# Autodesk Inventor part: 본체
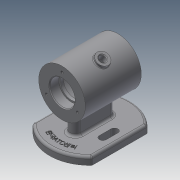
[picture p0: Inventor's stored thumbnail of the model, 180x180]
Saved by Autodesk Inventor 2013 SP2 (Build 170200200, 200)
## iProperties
Created: 2022-02
Part Number: 본체
Material: Generic
Document SubType Name: Modeling
Designer: a
Density: 1 g/cm^3
Author: a
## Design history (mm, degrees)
sketch "스케치1"
  geometry: L1 (-36, 0)-(36, 0); L2 (-36, 0)-(-36, 30); L3 (-36, 30)-(36, 30); L4 (36, 30)-(36, 0); L5 (-36, 16)-(-24, 16); L6 (-24, 16)-(-24, 14); L7 (-24, 14)-(-20, 14); L8 (-20, 14)-(-20, 25); L9 (-20, 25)-(20, 25); L10 (20, 25)-(20, 14); L11 (20, 14)-(24, 14); L12 (24, 14)-(24, 16); L13 (24, 16)-(36, 16); 2 further points
  constraints: 26 end point, 7 parallel, 4 perpendicular, 2 point on line, 1 coincident, 1 collinear, 1 horizontal, 1 midpoint
  dimensions: "d0" = 72 distance of L1.start L1.end; "d1" = 60 diameter of L3 L1; "d3" = 32 diameter of L5 L1; "d4" = 28 diameter of L7 L1; "d5" = 50 diameter of L9 L1; "d6" = 28 diameter of L11 L1; "d7" = 32 diameter of L13 L1; "d8" = 12 distance between parallel lines of L2 L6; "d9" = 40 distance between parallel lines of L10 L8; "d10" = 12 distance between parallel lines of L4 L12; "d11" = 4 distance between parallel lines of L6 L8
revolve "회전1" sketch "스케치1" stored, may be unused: angle "d12" = 90 deg
fillet "모깎기1" dims "d13" = 3
fillet "모깎기2" dims "d14" = 0.3
chamfer "모따기1" distance "d15" = 1; stored, may be unused: second distance "d16" = 2, angle "d17" = 45 deg
node "작업 평면1"
sketch "스케치2"
  geometry: C1 r 52 at (0, 0); 1 further point
  constraints: 1 centre point, 1 coincident
  dimensions: "d19" = 104 diameter of C1
extrude "돌출1" join sketch "스케치2" distance "d20" = 10; taper "d21" = 0 deg
sketch "스케치3"
  geometry: L1 (-35.496, 38)-(35.496, 38); L2 (-35.496, -38)-(35.496, -38); A1 r 52 centre (0, 0) between (-35.496, 38) and (35.496, 38) reference
  constraints: 4 end point, 4 point on circle, 1 horizontal, 1 parallel
  dimensions: "d22" = 76 distance between parallel lines of L2 L1; "d23" = 38 distance from line of L2 A1.centre
extrude "돌출2" cut sketch "스케치3" stored distance "d24" = 10; taper "d25" = 0 deg
sketch "스케치4"
  geometry: L1 (-19, 7)-(19, 7); L2 (19, 7)-(19, -7); L3 (19, -7)-(-19, -7); L4 (-19, -7)-(-19, 7); L5 (-19, 7)-(19, -7); L6 (19, 7)-(-19, -7); C1 r 7 at (19, 0); C2 r 7 at (-19, 0); A1 r 52 centre (0, 0) between (35.496, -38) and (35.496, 38) reference
  constraints: 12 end point, 4 midpoint, 2 centre point, 2 parallel, 1 horizontal, 1 perpendicular
  dimensions: "d26" = 38 distance of L2.end L3.end; "d27" = 14 distance of L1.end L2.end; "d28" = 14 diameter of C1; "d29" = 14 diameter of C2
extrude "돌출3" join sketch "스케치4" stored distance "d30" = 10; taper "d31" = 0 deg
sketch "스케치5"
  geometry: L1 (0, 0)-(0, 24); L2 (-7.5, 28.5)-(7.5, 28.5); L3 (7.5, 28.5)-(7.5, 19.5); L4 (7.5, 19.5)-(-7.5, 19.5); L5 (-7.5, 19.5)-(-7.5, 28.5); L6 (-7.5, 28.5)-(7.5, 19.5); L7 (7.5, 28.5)-(-7.5, 19.5); C1 r 4.5 at (7.5, 24); C2 r 4.5 at (-7.5, 24); A1 r 52 centre (0, 0) between (-35.496, 38) and (-35.496, -38) reference; A2 r 52 centre (0, 0) between (35.496, -38) and (35.496, 38) reference; 1 further point
  constraints: 14 end point, 5 midpoint, 2 centre point, 2 parallel, 1 horizontal, 1 perpendicular, 1 vertical alignment
  dimensions: "d34" = 24 distance of L1.start L1.end; "d35" = 15 distance of L3.end L4.end; "d36" = 9 distance of L2.end L3.end; "d37" = 9 diameter of C1; "d38" = 9 diameter of C2
extrude "돌출4" cut sketch "스케치5" stored distance "d39" = 10; taper "d40" = 0 deg
sketch "스케치6"
  geometry: L1 (0, 0)-(28.579, 16.5); L2 (0, 0)-(33, 0); C1 r 30 at (0, 0) reference; 2 further points
  constraints: 4 end point, 1 coincident, 1 equal length, 1 horizontal
  dimensions: "d41" = 33 distance of L1.start L1.end; "d42" = 30 deg angle of L2 L1
node "작업 평면2"
sketch "스케치7"
  geometry: C1 r 8 at (0, 0); 2 further points
  constraints: 2 coincident, 1 centre point
  dimensions: "d43" = 16 diameter of C1
extrude "돌출5" join sketch "스케치7" stored distance "d44" = 10; taper "d45" = 0 deg
sketch "스케치8"
  geometry: C1 r 8 at (0, 0) reference; 1 further point
  constraints: 1 coincident
hole "구멍1" sketch "스케치8" at (0, 0) diameter "d46" = 8; stored, may be unused: countersink angle "d50" = 90 deg, drill point angle "d52" = 0 deg; dims "d47" = 6, "d48" = 4, "d49" = 2, "d51" = 8
fillet "모깎기3" dims "d53" = 1
chamfer "모따기2" distance "d54" = 1; stored, may be unused: second distance "d55" = 2, angle "d56" = 45 deg
sketch "스케치9"
  geometry: C1 r 30 at (0, 0) reference; 1 further point
  constraints: 1 vertical alignment
  dimensions: "d57" = 23 distance of point (0, 23) C1.centre
hole "구멍2" sketch "스케치9" at (0, 23) diameter "d58" = 3.242; stored, may be unused: countersink angle "d62" = 90 deg, drill point angle "d64" = 118 deg; dims "d59" = 8, "d60" = 4, "d61" = 2, "d63" = 10
fillet "모깎기4" dims "d68" = 3
fillet "모깎기5" dims "d69" = 3
sketch "스케치10"
  geometry: L1 (-34.293, 35)-(34.293, 35) reference; L2 (34.293, -35)-(-34.293, -35) reference; L3 (-7.5, -19.5)-(7.5, -19.5) reference; L4 (7.5, -28.5)-(-7.5, -28.5) reference; L5 (-7.5, 28.5)-(7.5, 28.5) reference; L6 (7.5, 19.5)-(-7.5, 19.5) reference; L7 (19, 10)-(-19, 10) reference; L8 (-19, -10)-(19, -10) reference; C1 r 42.5 at (0, 0); A1 r 49 centre (0, 0) between (-34.293, 35) and (-34.293, -35) reference; A2 r 49 centre (0, 0) between (34.293, -35) and (34.293, 35) reference; A3 r 4.5 centre (7.5, -24) between (7.5, -28.5) and (7.5, -19.5) reference; A4 r 4.5 centre (-7.5, -24) between (-7.5, -19.5) and (-7.5, -28.5) reference; A5 r 4.5 centre (7.5, 24) between (7.5, 19.5) and (7.5, 28.5) reference; A6 r 4.5 centre (-7.5, 24) between (-7.5, 28.5) and (-7.5, 19.5) reference; A7 r 10 centre (19, 0) between (19, -10) and (19, 10) reference; A8 r 10 centre (-19, 0) between (-19, 10) and (-19, -10) reference
  constraints: 1 centre point, 1 coincident
  dimensions: "d70" = 85 diameter of C1
sketch "스케치11"
  geometry: C1 r 42.5 at (0, 0) reference
  constraints: 1 other
feature "엠보싱1" sketch "스케치11" dims "d0" = 72, "d1" = 60, "d3" = 32, "d4" = 28, "d5" = 50, "d6" = 28, "d7" = 32, "d8" = 12, "d9" = 40, "d10" = 12, "d11" = 4, "d14" = 0.3, "d71" = 0.5, "d72" = 0
fillet "모깎기6" dims "d73" = 3
node "솔리드1"
mirror "대칭1"
pattern_circular "원형 패턴1" dims angle "d66" = 360 deg
mirror "대칭2"
other parameters: "d18" = -62
